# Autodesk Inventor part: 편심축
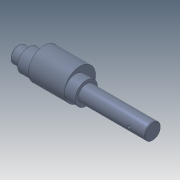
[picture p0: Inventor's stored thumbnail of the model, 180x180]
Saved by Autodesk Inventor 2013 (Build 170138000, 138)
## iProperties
Manager: 한국ATC센터
Company: 한국ATC센터
Created: 2014-07
Part Number: 편심축
Document SubType Name: Modeling
Designer: KYOUNG IL JANG
Density: 7.86 g/cm^3
Material: Steel, Mild
Mass: 1544.74 g
Surface Area: 256.354 cm^2
Volume: 196.531 cm^3
Author: KYOUNG IL JANG
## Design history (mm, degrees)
revolve "회전1" stored, may be unused: angle "d15" = 90 deg
revolve "회전2" stored, may be unused: angle "d16" = 90 deg
sketch "스케치1"
  geometry: L1 (-105, 0)-(105, 0); L2 (-105, 0)-(-105, 12.5); L3 (-105, 12.5)-(-89, 12.5); L4 (-89, 12.5)-(-89, 17.5); L5 (-89, 17.5)-(-82, 17.5); L6 (-82, 17.5)-(-82, 12.5); L7 (-82, 12.5)-(-0.35, 12.5); L8 (-0.35, 12.5)-(-0.35, 11.95); L9 (-0.35, 11.95)-(1, 11.95); L10 (1, 11.95)-(1, 12.5); L11 (1, 12.5)-(105, 12.5); L12 (105, 12.5)-(105, 0); L13 (70, 12.5)-(70, 9.1); L14 (70, 9.1)-(95, 9.1); L15 (95, 9.1)-(95, 12.5); L16 (80, -12.5)-(82.5, -12.5); L17 (82.5, -12.5)-(80, -10); L18 (80, -10)-(80, -12.5); L19 (1, 12.5)-(-0.35, 12.5); 2 further points
  constraints: 38 end point, 8 parallel, 5 collinear, 5 perpendicular, 2 point on line, 1 coincident, 1 horizontal, 1 midpoint, 1 vertical
  dimensions: "d0" = 210 distance of L1.start L1.end; "d1" = 25 diameter of L3 L1; "d2" = 35 diameter of L5 L1; "d3" = 16 distance of L2.end L3.end; "d6" = 1.35 distance of L8.end L9.end; "d7" = 23.9 diameter of L9 L1; "d8" = 3.4 distance between parallel lines of L14 L11; "d9" = 10 distance between parallel lines of L15 L12; "d10" = 25 distance of L13.end L14.end; "d11" = 25 diameter of L16 L1 (= d1); "d12" = 25 distance from line of L12 L16.start; "d13" = 45 deg angle of L17 L18; "d14" = 5 diameter of L16.end L18; "d27" = 104 distance between parallel lines of L10 L12; "d35" = 7 distance of L4.end L5.end
extrude "돌출1" cut sketch "스케치1" stored distance "d17" = 8; taper "d18" = 0 deg
fillet "모깎기1" dims "d19" = 4
node "작업 평면1"
sketch "스케치2"
  geometry: C1 r 12.5 at (0, 0) reference; C2 r 17.5 at (0, 0); C3 r 24.5 at (0, 7); 1 further point
  constraints: 2 centre point, 1 coincident, 1 tangent, 1 vertical alignment
  dimensions: "d32" = 35 diameter of C2; "d33" = 49 diameter of C3 (derived); "d34" = 7 distance of C3.centre point (0, 0)
extrude "돌출2" join sketch "스케치2" distance "d22" = 56; taper "d23" = 0 deg
chamfer "모따기1" distance "d24" = 1; stored, may be unused: second distance "d25" = 2, angle "d26" = 45 deg
feature "면 이동1" dims "d31" = 83
node "솔리드1"
